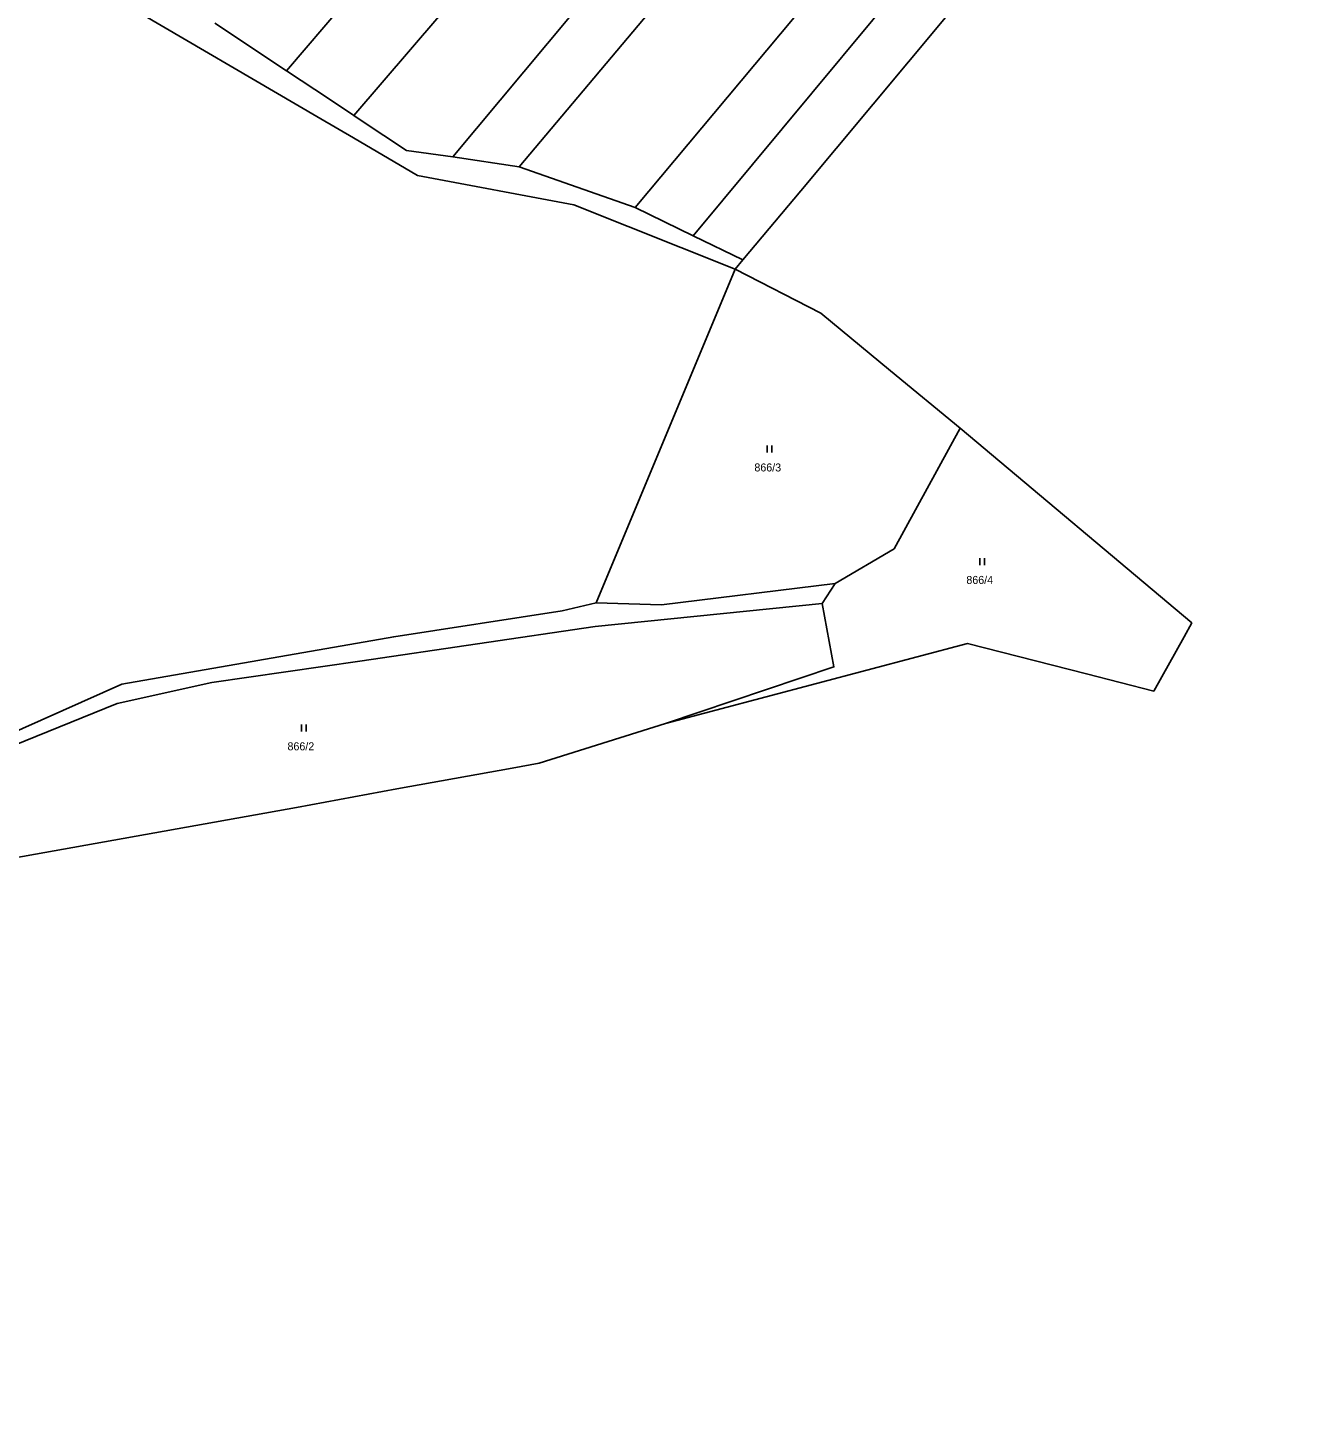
# Model space of a CAD drawing. Extents: x -751333 to -746055, y -1133395 to -1129777.
# Drawn here: x -747223.3 to -746952.1, y -1132213.1 to -1131915.2 of the extents above; entities that cross this region are included whole.
import ezdxf

# ---------------------------------------------------------------- set-up
doc = ezdxf.new("R2010")
doc.units = 0
for name, color, linetype in [('Hranice parcel', 7, 'Continuous'), ('Parcelní čísla', 7, 'Continuous'), ('Značky kultur', 7, 'Continuous')]:
    doc.layers.add(name, color=color, linetype=linetype)

msp = doc.modelspace()

# ---------------------------------------------------------------- linework, layer by layer
at = {"layer": 'Hranice parcel'}
for p, q in [((-747168.35, -1131924.28), (-747183.54, -1131914.17)), ((-747118.82, -1131944.76), (-747132.91, -1131942.59)), ((-747094.15, -1131953.41), (-747118.82, -1131944.76)), ((-747081.82, -1131959.38), (-747094.15, -1131953.41)), ((-747071.24, -1131964.51), (-747081.82, -1131959.38)), ((-747072.89, -1131966.47), (-747071.24, -1131964.51)), ((-747102.43, -1132037.5), (-747072.89, -1131966.47)), ((-747025.04, -1132000.35), (-747039.86, -1131988.12)), ((-747054.35, -1132037.66), (-747051.63, -1132033.4)), ((-746983.8, -1132056.28), (-746977.4, -1132044.75)), ((-746998.16, -1132052.61), (-746983.8, -1132056.28))]:
    msp.add_line(p, q, dxfattribs=at)
for points in [[(-747168.35, -1131924.28), (-747156.17, -1131910.12), (-747146.8, -1131899.23), (-747135.89, -1131886.55), (-747102.76, -1131847.44), (-747086.37, -1131828.14), (-747038.09, -1131772.55)], [(-747154.03, -1131933.81), (-747087.71, -1131856.54), (-747020.83, -1131778.66)], [(-747132.91, -1131942.59), (-747102.75, -1131906.39), (-747000.3, -1131785.93)], [(-746987.72, -1131790.65), (-747085.59, -1131905.13), (-747118.82, -1131944.76)], [(-747094.15, -1131953.41), (-747029.41, -1131875.97), (-746964.65, -1131799.29)], [(-747081.82, -1131959.38), (-747018.32, -1131883), (-746952.09, -1131804)], [(-747072.89, -1131966.47), (-747107.18, -1131952.81), (-747140.46, -1131946.56), (-747154.1, -1131938.56), (-747161.04, -1131934.49), (-747204.18, -1131909.18), (-747226.07, -1131896.73), (-747265.2, -1131885.54)], [(-747020.64, -1131903.85), (-747058.92, -1131949.83), (-747071.24, -1131964.51)], [(-747154.03, -1131933.81), (-747159.2, -1131930.37), (-747168.35, -1131924.28)], [(-747132.91, -1131942.59), (-747142.83, -1131941.27), (-747152.45, -1131934.86), (-747154.03, -1131933.81)], [(-747039.86, -1131988.12), (-747054.69, -1131975.89), (-747072.89, -1131966.47)], [(-747051.63, -1132033.4), (-747039.08, -1132026.03), (-747025.04, -1132000.35)], [(-746977.4, -1132044.75), (-746975.74, -1132041.76), (-747025.04, -1132000.35)], [(-747051.63, -1132033.4), (-747088.58, -1132037.93), (-747102.43, -1132037.5)], [(-747299.75, -1132213.05), (-747296.34, -1132200.82), (-747282.88, -1132149.41), (-747269.58, -1132097.49), (-747245.11, -1132073.4), (-747236.79, -1132069.7), (-747224.47, -1132064.21), (-747203.37, -1132054.82), (-747145.49, -1132044.7), (-747109.66, -1132039.16), (-747102.43, -1132037.5)], [(-747263.75, -1132103.85), (-747263.48, -1132094.73), (-747243.01, -1132076.52), (-747239.61, -1132074.64), (-747229.58, -1132069.12), (-747226.57, -1132067.9), (-747204.37, -1132058.93), (-747184.23, -1132054.46), (-747152.75, -1132049.88), (-747102.63, -1132042.55), (-747054.35, -1132037.66)], [(-747087.7, -1132063.18), (-747051.87, -1132051.13), (-747054.35, -1132037.66)], [(-747087.7, -1132063.18), (-747023.43, -1132046.16), (-746998.16, -1132052.61)], [(-747120.33, -1132072.66), (-747114.6, -1132071.63), (-747087.7, -1132063.18)], [(-747228.47, -1132092.15), (-747166.2, -1132081.01), (-747144.88, -1132077.08), (-747120.33, -1132072.66)]]:
    msp.add_lwpolyline(points, dxfattribs=at)
at = {"layer": 'Značky kultur'}
for p, q in [((-747066.101, -1132005.49), (-747066.101, -1132003.99)), ((-747065.1, -1132005.49), (-747065.1, -1132003.99)), ((-747020.851, -1132029.49), (-747020.851, -1132027.99)), ((-747019.85, -1132029.49), (-747019.85, -1132027.99)), ((-747165.131, -1132064.87), (-747165.131, -1132063.37)), ((-747164.13, -1132064.87), (-747164.13, -1132063.37))]:
    msp.add_line(p, q, dxfattribs=at)

# ---------------------------------------------------------------- texts
at = {"layer": 'Parcelní čísla'}
for s, p in [('866/3', (-747068.79, -1132009.54)), ('866/4', (-747023.7, -1132033.47)), ('866/2', (-747168.11, -1132068.87))]:
    msp.add_text(s, height=1.7, dxfattribs=at).set_placement(p)

doc.saveas('drawing.dxf')
